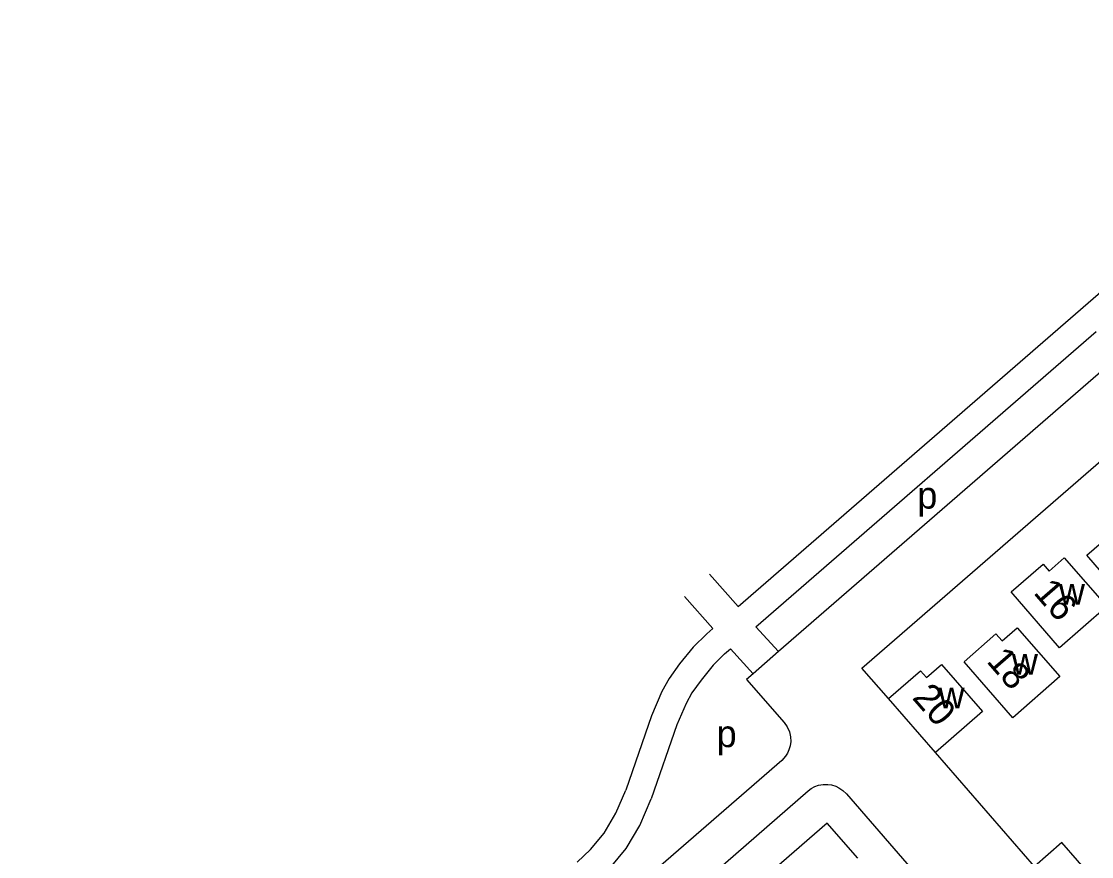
# Model space of a CAD drawing. Extents: x 155854 to 157362, y 383621 to 384685.
# Drawn here: x 156026.3 to 156185.4, y 384224.7 to 384348.9 of the extents above; entities that cross this region are included whole.
import ezdxf

# ---------------------------------------------------------------- set-up
doc = ezdxf.new("R2010")
doc.units = 0
for name, color, linetype in [('BLT_Basislijn', 7, 'Continuous'), ('BLT_Bebouwing', 7, 'Continuous'), ('BLT_Centroide', 7, 'Continuous'), ('BLT_Huisnummer', 7, 'Continuous')]:
    doc.layers.add(name, color=color, linetype=linetype)

msp = doc.modelspace()

# ---------------------------------------------------------------- linework, layer by layer
at = {"layer": 'BLT_Basislijn'}
for p, q in [((156132.85, 384261.87), (156233.02, 384348.89)), ((156135.5, 384258.87), (156186.06, 384302.79)), ((156189.53, 384299.17), (156138.87, 384255.17)), ((156132.85, 384261.87), (156128.62, 384266.68)), ((156129.08, 384258.59), (156124.88, 384263.36)), ((156128.22, 384257.84), (156129.08, 384258.59)), ((156135.5, 384258.87), (156138.87, 384255.17)), ((156130.84, 384254.82), (156131.73, 384255.59)), ((156131.73, 384255.59), (156135.09, 384251.89)), ((156138.87, 384255.17), (156135.09, 384251.89)), ((156135.09, 384251.89), (156134.12, 384251.04)), ((156134.12, 384251.04), (156139.7, 384244.62)), ((156119.97, 384245.61), (156116.16, 384234.58)), ((156123.75, 384244.31), (156119.94, 384233.27)), ((156139.33, 384239), (156052.94, 384163.95)), ((156176.89, 384223.23), (156162.2, 384240.16)), ((156026.31, 384132.88), (156143.26, 384234.47)), ((156148.96, 384234.01), (156182.91, 384194.98))]:
    msp.add_line(p, q, dxfattribs=at)
for points in [[(156155.19, 384248.2), (156151.27, 384252.7), (156196.87, 384292.31)], [(156128.22, 384257.84), (156126.19, 384255.86), (156124.16, 384253.37), (156122.61, 384251.19), (156121.51, 384249.24), (156119.97, 384245.61)], [(156130.84, 384254.82), (156129.15, 384253.16), (156127.35, 384250.94), (156125.99, 384249.04), (156125.11, 384247.47), (156123.75, 384244.31)], [(156139.7, 384244.62), (156140.15, 384243.97), (156140.48, 384243.27), (156140.65, 384242.52), (156140.67, 384241.81), (156140.6, 384241.18), (156140.41, 384240.55), (156140.19, 384240.05), (156139.91, 384239.64), (156139.33, 384239)], [(156108.92, 384223.85), (156110.92, 384225.77), (156112.94, 384228.19), (156114.66, 384231.15), (156116.16, 384234.58)], [(156143.26, 384234.47), (156143.7, 384234.8), (156144.26, 384235.11), (156144.82, 384235.3), (156145.5, 384235.43), (156146.17, 384235.43), (156146.75, 384235.34), (156147.39, 384235.15), (156147.84, 384234.93), (156148.44, 384234.53), (156148.96, 384234.01), (156148.9, 384234.08)], [(156111.55, 384220.83), (156113.84, 384223.04), (156116.23, 384225.88), (156118.23, 384229.34), (156119.94, 384233.27)], [(156150.65, 384224.45), (156146.11, 384229.67), (156055.9, 384151.3), (156072.3, 384132.42)]]:
    msp.add_lwpolyline(points, dxfattribs=at)
at = {"layer": 'BLT_Bebouwing'}
msp.add_line((156162.2, 384240.16), (156155.19, 384248.2), dxfattribs=at)
for points in [[(156190.34, 384272.61), (156192.59, 384274.57), (156198.92, 384267.29), (156191.88, 384261.2), (156184.67, 384269.52), (156189.43, 384273.65), (156190.34, 384272.61)], [(156179.09, 384267.16), (156181.34, 384269.14), (156187.66, 384261.86), (156180.64, 384255.76), (156173.43, 384264.05), (156178.18, 384268.19), (156179.09, 384267.16)], [(156172.09, 384256.76), (156174.36, 384258.73), (156180.69, 384251.46), (156173.69, 384245.31), (156166.45, 384253.66), (156171.19, 384257.8), (156172.09, 384256.76)], [(156155.19, 384248.2), (156159.95, 384252.34), (156160.85, 384251.31)], [(156160.85, 384251.31), (156163.1, 384253.26), (156169.2, 384246.26)], [(156169.2, 384246.26), (156162.2, 384240.16)], [(156189.28, 384224.58), (156185.65, 384221.42), (156180.99, 384226.79), (156176.89, 384223.23)]]:
    msp.add_lwpolyline(points, dxfattribs=at)

# ---------------------------------------------------------------- texts
at = {"layer": 'BLT_Centroide'}
for s, p in [('p', (156159.49, 384276.44)), ('w', (156180.55, 384262.16)), ('w', (156173.56, 384251.75)), ('w', (156162.65, 384246.72)), ('p', (156129.66, 384240.97))]:
    msp.add_text(s, height=4, dxfattribs=at).set_placement(p)
at = {"layer": 'BLT_Huisnummer'}
for s, p in [('16', (156176.64, 384263.89)), ('18', (156169.66, 384253.69)), ('20', (156158.61, 384248.26))]:
    msp.add_text(s, height=4, rotation=310.9787, dxfattribs=at).set_placement(p)

doc.saveas('drawing.dxf')
